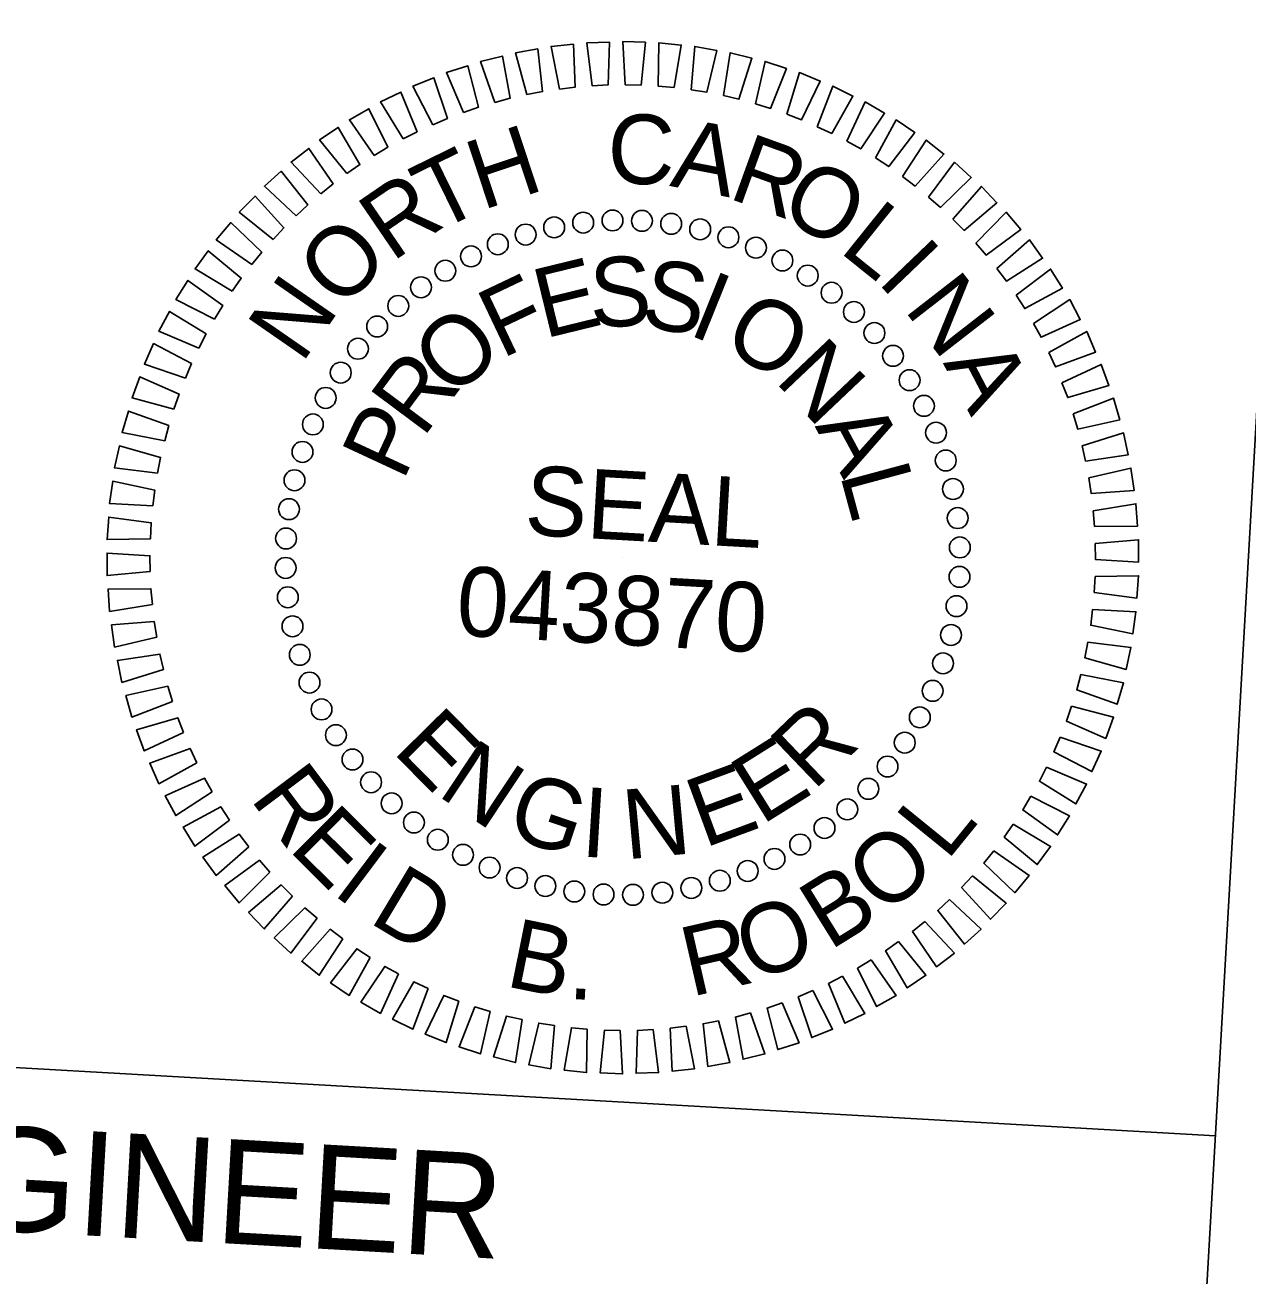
# Model space of a CAD drawing. Extents: x 2601627 to 2606907, y 616646 to 620530.
# Drawn here: x 2605867.9 to 2606131.5, y 617309.3 to 617578.9 of the extents above; entities that cross this region are included whole.
import ezdxf

# ---------------------------------------------------------------- set-up
doc = ezdxf.new("R2010")
doc.units = 0
doc.layers.add('Sheet PE Seal Cell', color=7, linetype='Continuous')
doc.layers.add('Sheet Title CELL', color=7, linetype='Continuous')

msp = doc.modelspace()

# ---------------------------------------------------------------- linework, layer by layer
at = {"layer": 'Sheet PE Seal Cell'}
msp.add_line((2605996.87, 617464.02), (2605996.87, 617464.02), dxfattribs=at)
for points in [[(2605976.19, 617563.88), (2605973.75, 617572.91), (2605978.53, 617573.73), (2605979.55, 617564.54)], [(2605983.21, 617565.07), (2605981.4, 617574.26), (2605986.23, 617574.74), (2605986.61, 617565.5)], [(2605990.29, 617565.78), (2605989.13, 617575.07), (2605993.98, 617575.22), (2605993.71, 617565.97)], [(2605997.4, 617565.99), (2605996.9, 617575.34), (2606001.74, 617575.15), (2606000.83, 617565.94)], [(2606004.51, 617565.71), (2606004.66, 617575.07), (2606009.48, 617574.54), (2606007.93, 617565.42)], [(2606011.59, 617564.93), (2606012.39, 617574.25), (2606017.16, 617573.39), (2606014.97, 617564.4)], [(2605969.27, 617562.19), (2605966.21, 617571.04), (2605970.92, 617572.19), (2605972.58, 617563.08)], [(2606018.59, 617563.65), (2606020.04, 617572.9), (2606024.74, 617571.71), (2606021.93, 617562.89)], [(2606025.49, 617561.9), (2606027.58, 617571.02), (2606032.18, 617569.5), (2606028.77, 617560.9)], [(2605962.49, 617560.03), (2605958.82, 617568.64), (2605963.44, 617570.11), (2605965.73, 617561.15)], [(2606032.25, 617559.66), (2606034.97, 617568.62), (2606039.46, 617566.78), (2606035.45, 617558.44)], [(2605955.88, 617557.39), (2605951.62, 617565.73), (2605956.12, 617567.52), (2605959.03, 617558.74)], [(2606038.83, 617556.96), (2606042.17, 617565.71), (2606046.52, 617563.56), (2606041.94, 617555.52)], [(2605949.47, 617554.31), (2605944.63, 617562.32), (2605949, 617564.43), (2605952.52, 617555.87)], [(2605943.28, 617550.78), (2605937.9, 617558.44), (2605942.11, 617560.84), (2605946.22, 617552.55)], [(2606045.21, 617553.81), (2606049.16, 617562.3), (2606053.34, 617559.85), (2606048.21, 617552.15)], [(2606051.36, 617550.22), (2606055.88, 617558.41), (2606059.89, 617555.68), (2606054.24, 617548.35)], [(2605937.36, 617546.83), (2605931.46, 617554.1), (2605935.49, 617556.79), (2605940.17, 617548.8)], [(2605931.73, 617542.48), (2605925.34, 617549.32), (2605929.17, 617552.28), (2605934.39, 617544.64)], [(2606057.24, 617546.2), (2606062.32, 617554.07), (2606066.13, 617551.06), (2606059.98, 617544.15)], [(2606062.82, 617541.79), (2606068.45, 617549.28), (2606072.03, 617546.02), (2606065.41, 617539.55)], [(2605926.42, 617537.74), (2605919.56, 617544.12), (2605923.18, 617547.34), (2605928.92, 617540.09)], [(2606068.09, 617537), (2606074.22, 617544.08), (2606077.57, 617540.57), (2606070.52, 617534.58)], [(2605921.45, 617532.65), (2605914.16, 617538.53), (2605917.55, 617542), (2605923.78, 617535.16)], [(2606073, 617531.86), (2606079.61, 617538.49), (2606082.71, 617534.76), (2606075.26, 617529.28)], [(2605916.84, 617527.22), (2605909.17, 617532.58), (2605912.3, 617536.28), (2605918.99, 617529.89)], [(2606077.55, 617526.38), (2606084.61, 617532.54), (2606087.44, 617528.6), (2606079.62, 617523.65)], [(2605912.63, 617521.49), (2605904.6, 617526.29), (2605907.47, 617530.2), (2605914.59, 617524.3)], [(2606081.7, 617520.6), (2606089.17, 617526.25), (2606091.72, 617522.12), (2606083.58, 617517.73)], [(2605908.83, 617515.47), (2605900.48, 617519.71), (2605903.07, 617523.81), (2605910.59, 617518.41)], [(2606085.44, 617514.55), (2606093.29, 617519.66), (2606095.54, 617515.37), (2606087.11, 617511.55)], [(2605905.45, 617509.2), (2605896.83, 617512.85), (2605899.13, 617517.12), (2605907, 617512.26)], [(2606088.75, 617508.24), (2606096.94, 617512.8), (2606098.88, 617508.36), (2606090.21, 617505.14)], [(2605902.52, 617502.72), (2605893.67, 617505.75), (2605895.66, 617510.17), (2605903.86, 617505.87)], [(2606091.61, 617501.73), (2606100.09, 617505.7), (2606101.73, 617501.13), (2606092.85, 617498.53)], [(2605900.05, 617496.04), (2605891.01, 617498.45), (2605892.69, 617503), (2605901.16, 617499.28)], [(2606094.01, 617495.03), (2606102.75, 617498.4), (2606104.06, 617493.73), (2606095.02, 617491.75)], [(2605898.06, 617489.21), (2605888.86, 617490.98), (2605890.22, 617495.63), (2605898.94, 617492.52)], [(2606095.94, 617488.17), (2606104.89, 617490.93), (2606105.87, 617486.18), (2606096.72, 617484.84)], [(2605896.54, 617482.25), (2605887.25, 617483.38), (2605888.28, 617488.12), (2605897.19, 617485.62)], [(2606097.38, 617481.2), (2606106.5, 617483.32), (2606107.15, 617478.52), (2606097.93, 617477.82)], [(2605895.51, 617475.21), (2605886.16, 617475.69), (2605886.86, 617480.48), (2605895.92, 617478.61)], [(2606098.34, 617474.15), (2606107.58, 617475.63), (2606107.9, 617470.79), (2606098.64, 617470.74)], [(2605894.98, 617468.11), (2605885.62, 617467.93), (2605885.98, 617472.77), (2605895.15, 617471.54)], [(2606098.8, 617467.05), (2606108.12, 617467.88), (2606108.1, 617463.03), (2606098.86, 617463.62)], [(2605894.94, 617461), (2605885.62, 617460.16), (2605885.64, 617465.01), (2605894.88, 617464.42)], [(2606098.76, 617459.93), (2606108.12, 617460.11), (2606107.76, 617455.27), (2606098.59, 617456.51)], [(2605895.4, 617453.89), (2605886.16, 617452.41), (2605885.84, 617457.25), (2605895.1, 617457.31)], [(2606098.23, 617452.83), (2606107.58, 617452.36), (2606106.88, 617447.56), (2606097.81, 617449.43)], [(2605896.36, 617446.84), (2605887.24, 617444.72), (2605886.59, 617449.52), (2605895.81, 617450.22)], [(2606097.2, 617445.79), (2606106.49, 617444.66), (2606105.46, 617439.93), (2606096.55, 617442.42)], [(2605897.8, 617439.87), (2605888.85, 617437.12), (2605887.87, 617441.87), (2605897.02, 617443.21)], [(2606095.68, 617438.84), (2606104.88, 617437.06), (2606103.52, 617432.41), (2606094.8, 617435.52)], [(2605899.72, 617433.02), (2605890.99, 617429.65), (2605889.68, 617434.32), (2605898.72, 617436.29)], [(2606093.68, 617432), (2606102.73, 617429.6), (2606101.05, 617425.05), (2606092.58, 617428.76)], [(2605902.12, 617426.32), (2605893.65, 617422.35), (2605892.01, 617426.91), (2605900.89, 617429.51)], [(2606091.22, 617425.33), (2606100.07, 617422.3), (2606098.08, 617417.88), (2606089.88, 617422.17)], [(2605904.99, 617419.8), (2605896.8, 617415.25), (2605894.85, 617419.69), (2605903.53, 617422.9)], [(2606088.29, 617418.84), (2606096.91, 617415.2), (2606094.61, 617410.93), (2606086.74, 617415.79)], [(2605908.29, 617413.5), (2605900.45, 617408.39), (2605898.19, 617412.68), (2605906.63, 617416.49)], [(2606084.91, 617412.58), (2606093.26, 617408.34), (2606090.67, 617404.24), (2606083.15, 617409.63)], [(2605912.03, 617407.44), (2605904.57, 617401.8), (2605902.02, 617405.92), (2605910.16, 617410.31)], [(2606081.11, 617406.56), (2606089.14, 617401.75), (2606086.27, 617397.84), (2606079.15, 617403.75)], [(2605916.19, 617401.66), (2605909.13, 617395.51), (2605906.3, 617399.45), (2605914.12, 617404.4)], [(2605920.73, 617396.19), (2605914.12, 617389.56), (2605911.03, 617393.29), (2605918.48, 617398.77)], [(2606076.9, 617400.82), (2606084.57, 617395.46), (2606081.44, 617391.77), (2606074.74, 617398.16)], [(2605925.65, 617391.04), (2605919.52, 617383.96), (2605916.17, 617387.47), (2605923.22, 617393.46)], [(2606072.29, 617395.39), (2606079.58, 617389.51), (2606076.19, 617386.04), (2606069.96, 617392.88)], [(2606067.32, 617390.3), (2606074.18, 617383.93), (2606070.56, 617380.7), (2606064.82, 617387.96)], [(2605930.92, 617386.25), (2605925.29, 617378.76), (2605921.71, 617382.03), (2605928.32, 617388.49)], [(2606062.01, 617385.57), (2606068.4, 617378.73), (2606064.57, 617375.76), (2606059.35, 617383.4)], [(2605936.5, 617381.84), (2605931.41, 617373.98), (2605927.61, 617376.98), (2605933.76, 617383.9)], [(2605942.38, 617377.83), (2605937.86, 617369.63), (2605933.85, 617372.36), (2605939.5, 617379.69)], [(2606056.38, 617381.21), (2606062.28, 617373.95), (2606058.25, 617371.25), (2606053.57, 617379.24)], [(2606050.45, 617377.26), (2606055.84, 617369.6), (2606051.62, 617367.2), (2606047.52, 617375.49)], [(2605948.53, 617374.24), (2605944.58, 617365.75), (2605940.4, 617368.19), (2605945.53, 617375.89)], [(2605954.91, 617371.08), (2605951.57, 617362.34), (2605947.22, 617364.49), (2605951.8, 617372.53)], [(2606044.27, 617373.74), (2606049.11, 617365.72), (2606044.74, 617363.62), (2606041.22, 617372.18)], [(2605961.49, 617368.38), (2605958.77, 617359.43), (2605954.28, 617361.26), (2605958.29, 617369.61)], [(2606037.86, 617370.65), (2606042.12, 617362.32), (2606037.62, 617360.52), (2606034.71, 617369.31)], [(2605968.25, 617366.15), (2605966.16, 617357.02), (2605961.55, 617358.54), (2605964.97, 617367.14)], [(2606031.24, 617368.02), (2606034.92, 617359.41), (2606030.3, 617357.93), (2606028.01, 617366.9)], [(2605975.15, 617364.39), (2605973.7, 617355.14), (2605969, 617356.34), (2605971.81, 617365.15)], [(2605982.15, 617363.12), (2605981.35, 617353.79), (2605976.58, 617354.66), (2605978.76, 617363.65)], [(2606017.55, 617364.17), (2606019.99, 617355.13), (2606015.21, 617354.31), (2606014.19, 617363.51)], [(2606024.46, 617365.85), (2606027.53, 617357.01), (2606022.82, 617355.86), (2606021.16, 617364.96)], [(2605989.22, 617362.34), (2605989.08, 617352.98), (2605984.26, 617353.51), (2605985.81, 617362.63)], [(2605996.34, 617362.05), (2605996.84, 617352.7), (2605992, 617352.9), (2605992.91, 617362.1)], [(2606003.45, 617362.26), (2606004.61, 617352.97), (2605999.76, 617352.83), (2606000.03, 617362.08)], [(2606010.53, 617362.97), (2606012.33, 617353.78), (2606007.51, 617353.3), (2606007.13, 617362.55)]]:
    msp.add_lwpolyline(points, close=True, dxfattribs=at)
for centre in [(2605988.33, 617536.27), (2605994.66, 617536.74), (2606001.01, 617536.65), (2605975.92, 617533.69), (2605982.07, 617535.25), (2606007.32, 617536.02), (2606013.56, 617534.83), (2605969.92, 617531.6), (2606019.66, 617533.11), (2606025.6, 617530.86), (2605964.14, 617528.99), (2606031.31, 617528.1), (2605958.6, 617525.89), (2606036.77, 617524.85), (2605953.35, 617522.32), (2606041.92, 617521.15), (2605948.44, 617518.31), (2606046.73, 617517), (2605943.89, 617513.88), (2606051.15, 617512.46), (2605939.75, 617509.07), (2606055.17, 617507.54), (2605936.04, 617503.92), (2606058.74, 617502.29), (2605932.79, 617498.47), (2606061.84, 617496.76), (2605930.03, 617492.75), (2606064.45, 617490.97), (2605927.78, 617486.82), (2606066.54, 617484.98), (2605926.06, 617480.71), (2606068.1, 617478.82), (2605924.87, 617474.47), (2606069.12, 617472.56), (2605924.24, 617468.16), (2606069.59, 617466.23), (2605924.15, 617461.81), (2606069.5, 617459.88), (2605924.62, 617455.48), (2606068.86, 617453.57), (2605925.64, 617449.22), (2606067.68, 617447.34), (2605927.2, 617443.07), (2606065.96, 617441.23), (2605929.29, 617437.08), (2606063.71, 617435.29), (2605931.9, 617431.29), (2606060.95, 617429.58), (2605935, 617425.75), (2606057.7, 617424.12), (2605938.57, 617420.5), (2606053.99, 617418.97), (2605942.58, 617415.59), (2606049.85, 617414.17), (2605947.01, 617411.04), (2606045.3, 617409.74), (2605951.82, 617406.9), (2606040.39, 617405.72), (2605956.97, 617403.19), (2606035.14, 617402.15), (2605962.42, 617399.94), (2606029.6, 617399.05), (2605968.14, 617397.19), (2606023.82, 617396.45), (2605974.07, 617394.94), (2606017.82, 617394.35), (2605980.18, 617393.21), (2605986.42, 617392.03), (2605992.73, 617391.39), (2605999.08, 617391.31), (2606005.41, 617391.77), (2606011.67, 617392.79)]:
    msp.add_circle(centre, 2.25, dxfattribs=at)
at = {"layer": 'Sheet Title CELL'}
for p, q in [((2606111.05, 617099.66), (2606138.35, 617578.89)), ((2605463.77, 617376.99), (2606124.7, 617339.35))]:
    msp.add_line(p, q, dxfattribs=at)

# ---------------------------------------------------------------- texts
at = {"layer": 'Sheet PE Seal Cell'}
for s, rotation, p in [('C', 358.7016, (2605993.45, 617544.75)), ('A', 349.1966, (2606006.82, 617544.2)), ('H', 18.3408, (2605966.52, 617538.9)), ('R', 340.1491, (2606019.31, 617541.64)), ('T', 26.13, (2605956.65, 617534.09)), ('O', 331.9404, (2606030.16, 617537.64)), ('R', 34.3387, (2605947.06, 617527.63)), ('L', 321.2152, (2606043.28, 617530.16)), ('O', 45.0639, (2605936.09, 617517.25)), ('I', 313.7501, (2606051.48, 617523.57)), ('E', 13.7257, (2605979.94, 617511.23)), ('S', 1.9635, (2605989.91, 617513.69)), ('S', 350.0045, (2606000.36, 617514.05)), ('F', 25.4037, (2605970.73, 617506.82)), ('I', 338.0456, (2606010.65, 617512.24)), ('N', 307.8101, (2606057.35, 617517.6)), ('N', 55.2743, (2605927.61, 617505.64)), ('O', 329.2901, (2606017.83, 617509.58)), ('O', 41.2124, (2605960.06, 617498.08)), ('N', 313.4814, (2606029.45, 617502.15)), ('R', 53.3119, (2605953.74, 617489.61)), ('A', 297.5997, (2606065.89, 617506.03)), ('P', 65.0741, (2605949.43, 617480.28)), ('A', 298.4313, (2606038.23, 617492.38)), ('SEAL', 356.7398, (2605975.5, 617469)), ('L', 285.0954, (2606043.66, 617482.08)), ('043870', 356.7398, (2605960.71, 617447.3)), ('E', 314.5904, (2605946.98, 617422.22)), ('R', 43.7827, (2606037.97, 617413.55)), ('E', 32.0205, (2606026.82, 617406.23)), ('N', 326.3526, (2605956.55, 617412.92)), ('R', 306.9023, (2605916.29, 617412.08)), ('G', 341.4027, (2605971.2, 617404.21)), ('E', 20.2582, (2606014.41, 617401.34)), ('I', 356.4527, (2605987.62, 617399.6)), ('N', 5.2082, (2605997.53, 617398.94)), ('E', 315.111, (2605924.53, 617401.11)), ('L', 50.9158, (2606066.78, 617398.42)), ('O', 40.1906, (2606053.35, 617386.55)), ('I', 323.0908, (2605933.96, 617391.68)), ('D', 329.0308, (2605941.79, 617385.55)), ('B', 31.8485, (2606041.51, 617379.18)), ('O', 21.1233, (2606024.94, 617372.35)), ('B', 348.6033, (2605971.26, 617371.64)), ('R', 12.9147, (2606011.56, 617369.28)), ('.', 356.9454, (2605984.93, 617368.9))]:
    msp.add_text(s, height=15, rotation=rotation, dxfattribs=at).set_placement(p)
at = {"layer": 'Sheet Title CELL'}
msp.add_text('ROADWAY DESIGN ENGINEER', height=22.5, rotation=356.7403, dxfattribs=at).set_placement((2605526.45, 617338.07))

doc.saveas('drawing.dxf')
